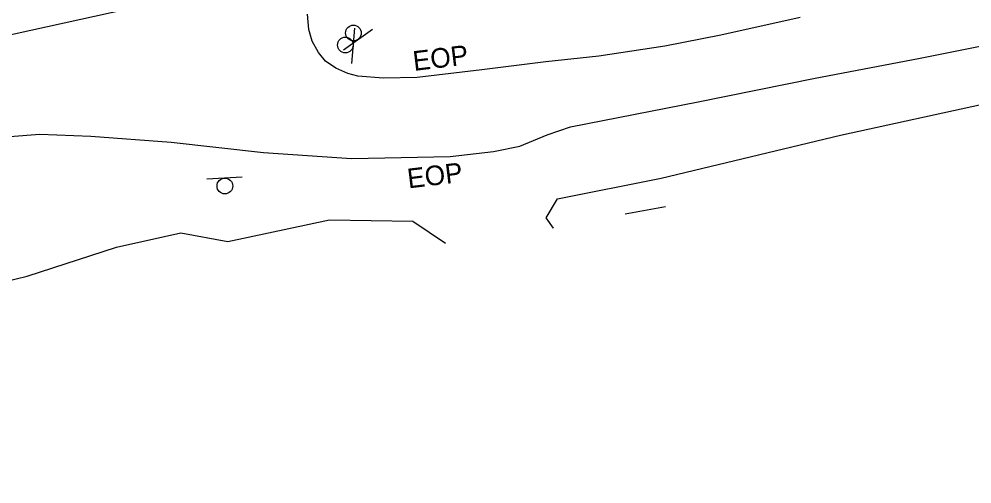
# Model space of a CAD drawing. Extents: x 2076109 to 2080761, y 592812 to 596750.
# Drawn here: x 2076714.3 to 2076956.7, y 595350.4 to 595468.6 of the extents above; entities that cross this region are included whole.
import ezdxf

# ---------------------------------------------------------------- set-up
doc = ezdxf.new("R2010")
doc.units = 0
for name, color, linetype in [('RD_EX_BldgApp', 7, 'Continuous'), ('RD_EX_Road', 7, 'Continuous'), ('RD_EX_Road_txCode', 7, 'Continuous'), ('RD_EX_UT', 7, 'Continuous'), ('RD_EX_VEG', 7, 'Continuous'), ('RD_PD_ALT2_CL', 7, 'Continuous')]:
    doc.layers.add(name, color=color, linetype=linetype)

msp = doc.modelspace()

# ---------------------------------------------------------------- linework, layer by layer
at = {"layer": 'RD_EX_BldgApp'}
for p, q in [((2076796.83, 595460.8), (2076804.17, 595466.01)), ((2076796.83, 595460.8), (2076804.17, 595466.01)), ((2076798.96, 595457.35), (2076799.67, 595466.32)), ((2076798.96, 595457.35), (2076799.67, 595466.32)), ((2076771.04, 595428.46), (2076762.06, 595427.94)), ((2076771.04, 595428.46), (2076762.06, 595427.94))]:
    msp.add_line(p, q, dxfattribs=at)
for centre in [(2076799.34, 595465.07), (2076799.34, 595465.07), (2076797.3, 595462.01), (2076797.3, 595462.01), (2076766.65, 595426.18), (2076766.65, 595426.18)]:
    msp.add_circle(centre, 2, dxfattribs=at)
at = {"layer": 'RD_EX_Road'}
for points in [[(2076711.91, 595438.8), (2076719.56, 595439.35), (2076732.54, 595438.88), (2076752.98, 595437.32), (2076776.45, 595434.66), (2076798.85, 595433.18), (2076807.36, 595433.37), (2076823.93, 595433.71), (2076834.97, 595434.98), (2076841.7, 595436.27), (2076848.64, 595439.18), (2076854.53, 595441.22), (2076887.04, 595447.57), (2076916.77, 595453.57), (2076943.1, 595458.61), (2076961.26, 595462.23), (2076993.16, 595466.83), (2077024.09, 595473.37), (2077049.42, 595477.24), (2077074.7, 595481.8), (2077096.12, 595486.28), (2077109.29, 595488.87)], [(2076711.91, 595438.8), (2076719.56, 595439.35), (2076732.54, 595438.88), (2076752.98, 595437.32), (2076776.45, 595434.66), (2076798.85, 595433.18), (2076807.36, 595433.37), (2076823.93, 595433.71), (2076834.97, 595434.98), (2076841.7, 595436.27), (2076848.64, 595439.18), (2076854.53, 595441.22), (2076887.04, 595447.57), (2076916.77, 595453.57), (2076943.1, 595458.61), (2076961.26, 595462.23), (2076993.16, 595466.83), (2077024.09, 595473.37), (2077049.42, 595477.24), (2077074.7, 595481.8), (2077096.12, 595486.28), (2077109.29, 595488.87)], [(2076913.01, 595469.05), (2076892.76, 595464.5), (2076878.56, 595461.73), (2076861.79, 595459.15), (2076848.32, 595457.78), (2076831.98, 595455.71), (2076815.54, 595453.78), (2076807, 595453.62), (2076800.49, 595454.09), (2076797.96, 595454.75), (2076794.91, 595456.15), (2076792.2, 595457.95), (2076790.48, 595460.11), (2076788.87, 595462.99), (2076787.98, 595465.96), (2076787.69, 595469.85)], [(2076913.01, 595469.05), (2076892.76, 595464.5), (2076878.56, 595461.73), (2076861.79, 595459.15), (2076848.32, 595457.78), (2076831.98, 595455.71), (2076815.54, 595453.78), (2076807, 595453.62), (2076800.49, 595454.09), (2076797.96, 595454.75), (2076794.91, 595456.15), (2076792.2, 595457.95), (2076790.48, 595460.11), (2076788.87, 595462.99), (2076787.98, 595465.96), (2076787.69, 595469.85)]]:
    msp.add_lwpolyline(points, dxfattribs=at)
at = {"layer": 'RD_EX_UT'}
msp.add_line((2076566.44, 595432.36), (2076937.84, 595514.77), dxfattribs=at)
msp.add_line((2076566.44, 595432.36), (2076937.84, 595514.77), dxfattribs=at)
at = {"layer": 'RD_EX_VEG'}
for points in [[(2076850.27, 595415.42), (2076850.21, 595415.45), (2076848.41, 595418.09), (2076851.21, 595422.91), (2076877.6, 595428.13), (2076923.27, 595439.11), (2076961.29, 595447.37), (2076966.08, 595443.67), (2076975.06, 595434.92), (2076996.96, 595435.3), (2077009.72, 595442.72), (2077013.66, 595449.51), (2077031.56, 595454.95), (2077051.21, 595459.83), (2077053.49, 595457.52), (2077055.07, 595448.52)], [(2076850.27, 595415.42), (2076850.21, 595415.45), (2076848.41, 595418.09), (2076851.21, 595422.91), (2076877.6, 595428.13), (2076923.27, 595439.11), (2076961.29, 595447.37), (2076966.08, 595443.67), (2076975.06, 595434.92), (2076996.96, 595435.3), (2077009.72, 595442.72), (2077013.66, 595449.51), (2077031.56, 595454.95), (2077051.21, 595459.83), (2077053.49, 595457.52), (2077055.07, 595448.52)], [(2076636.23, 595350.44), (2076629.1, 595358.09), (2076630.91, 595366.51), (2076641.43, 595373.25), (2076662.8, 595379.06), (2076684.62, 595389.11), (2076693.88, 595397.83), (2076716.37, 595403.24), (2076739.1, 595410.66), (2076755.46, 595414.28), (2076767.4, 595412.06), (2076793.28, 595417.54), (2076814.44, 595417.26), (2076822.78, 595411.67)], [(2076636.23, 595350.44), (2076629.1, 595358.09), (2076630.91, 595366.51), (2076641.43, 595373.25), (2076662.8, 595379.06), (2076684.62, 595389.11), (2076693.88, 595397.83), (2076716.37, 595403.24), (2076739.1, 595410.66), (2076755.46, 595414.28), (2076767.4, 595412.06), (2076793.28, 595417.54), (2076814.44, 595417.26), (2076822.78, 595411.67)]]:
    msp.add_lwpolyline(points, dxfattribs=at)
at = {"layer": 'RD_PD_ALT2_CL'}
msp.add_line((2076878.71, 595420.88), (2076868.5, 595418.99), dxfattribs=at)
msp.add_line((2076878.71, 595420.88), (2076868.5, 595418.99), dxfattribs=at)

# ---------------------------------------------------------------- texts
at = {"layer": 'RD_EX_Road_txCode'}
for p in [(2076814.77, 595455.42), (2076814.77, 595455.42), (2076813.35, 595425.55), (2076813.35, 595425.55)]:
    msp.add_text('EOP', height=5, rotation=6.8735, dxfattribs=at).set_placement(p)

doc.saveas('drawing.dxf')
